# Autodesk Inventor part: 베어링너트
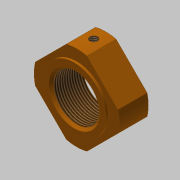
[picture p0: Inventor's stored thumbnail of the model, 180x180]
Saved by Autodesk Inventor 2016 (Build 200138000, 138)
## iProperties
Created: 2019-05
Part Number: 베어링너트
Material: 스테인리스강
Document SubType Name: Modeling
Designer: mduedu
Density: 1 g/cm^3
Appearance: 주황색
Author: mduedu
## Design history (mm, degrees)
sketch "스케치1"
  geometry: C1 r 17.5 at (0, 0); 1 further point
  constraints: 1 centre point, 1 coincident
  dimensions: "d0" = 35 diameter of C1
extrude "돌출1" new body sketch "스케치1" distance "d1" = 12; taper "d2" = 0 deg
sketch "스케치2"
  geometry: L1 (-21.213, 0)-(0, 21.213); L2 (0, 21.213)-(21.213, 0); L3 (21.213, 0)-(0, -21.213); L4 (0, -21.213)-(-21.213, 0); L5 (-21.213, 0)-(21.213, 0); L6 (0, 21.213)-(0, -21.213); 1 further point
  constraints: 12 end point, 2 midpoint, 2 parallel, 1 perpendicular, 1 vertical
  dimensions: "d3" = 30 distance of L1.end L2.end; "d5" = 30 distance of L2.end L3.end
extrude "돌출2" sketch "스케치2" stored distance "d6" = 12; taper "d7" = 0 deg
sketch "스케치3"
  geometry: C1 r 13 at (0, 0); 1 further point
  constraints: 1 centre point, 1 coincident
  dimensions: "d8" = 26 diameter of C1
extrude "돌출3" join sketch "스케치3" distance "d9" = 1; taper "d10" = 0 deg
hole "구멍1" diameter "d13" = 18.917; stored, may be unused: countersink angle "d17" = 90 deg, drill point angle "d19" = 118 deg; dims "d11" = 10, "d12" = 10, "d14" = 6, "d15" = 4, "d16" = 2, "d18" = 8
chamfer "모따기1" distance "d20" = 1; stored, may be unused: second distance "d21" = 2, angle "d22" = 45 deg
node "작업 평면1"
sketch "스케치5"
  geometry: L1 (-4.233, 0)-(4.233, 0) reference; 3 further points
  constraints: 1 midpoint, 1 vertical alignment
  dimensions: "d31" = 5 distance from line of point (0, 5) L1
hole "구멍3" sketch "스케치5" at (0, 5) diameter "d32" = 3.242; stored, may be unused: countersink angle "d36" = 90 deg, drill point angle "d38" = 118 deg; dims "d33" = 6, "d34" = 4, "d35" = 2, "d37" = 8
node "솔리드1"
